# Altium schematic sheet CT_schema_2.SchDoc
size 316 x 200 mm
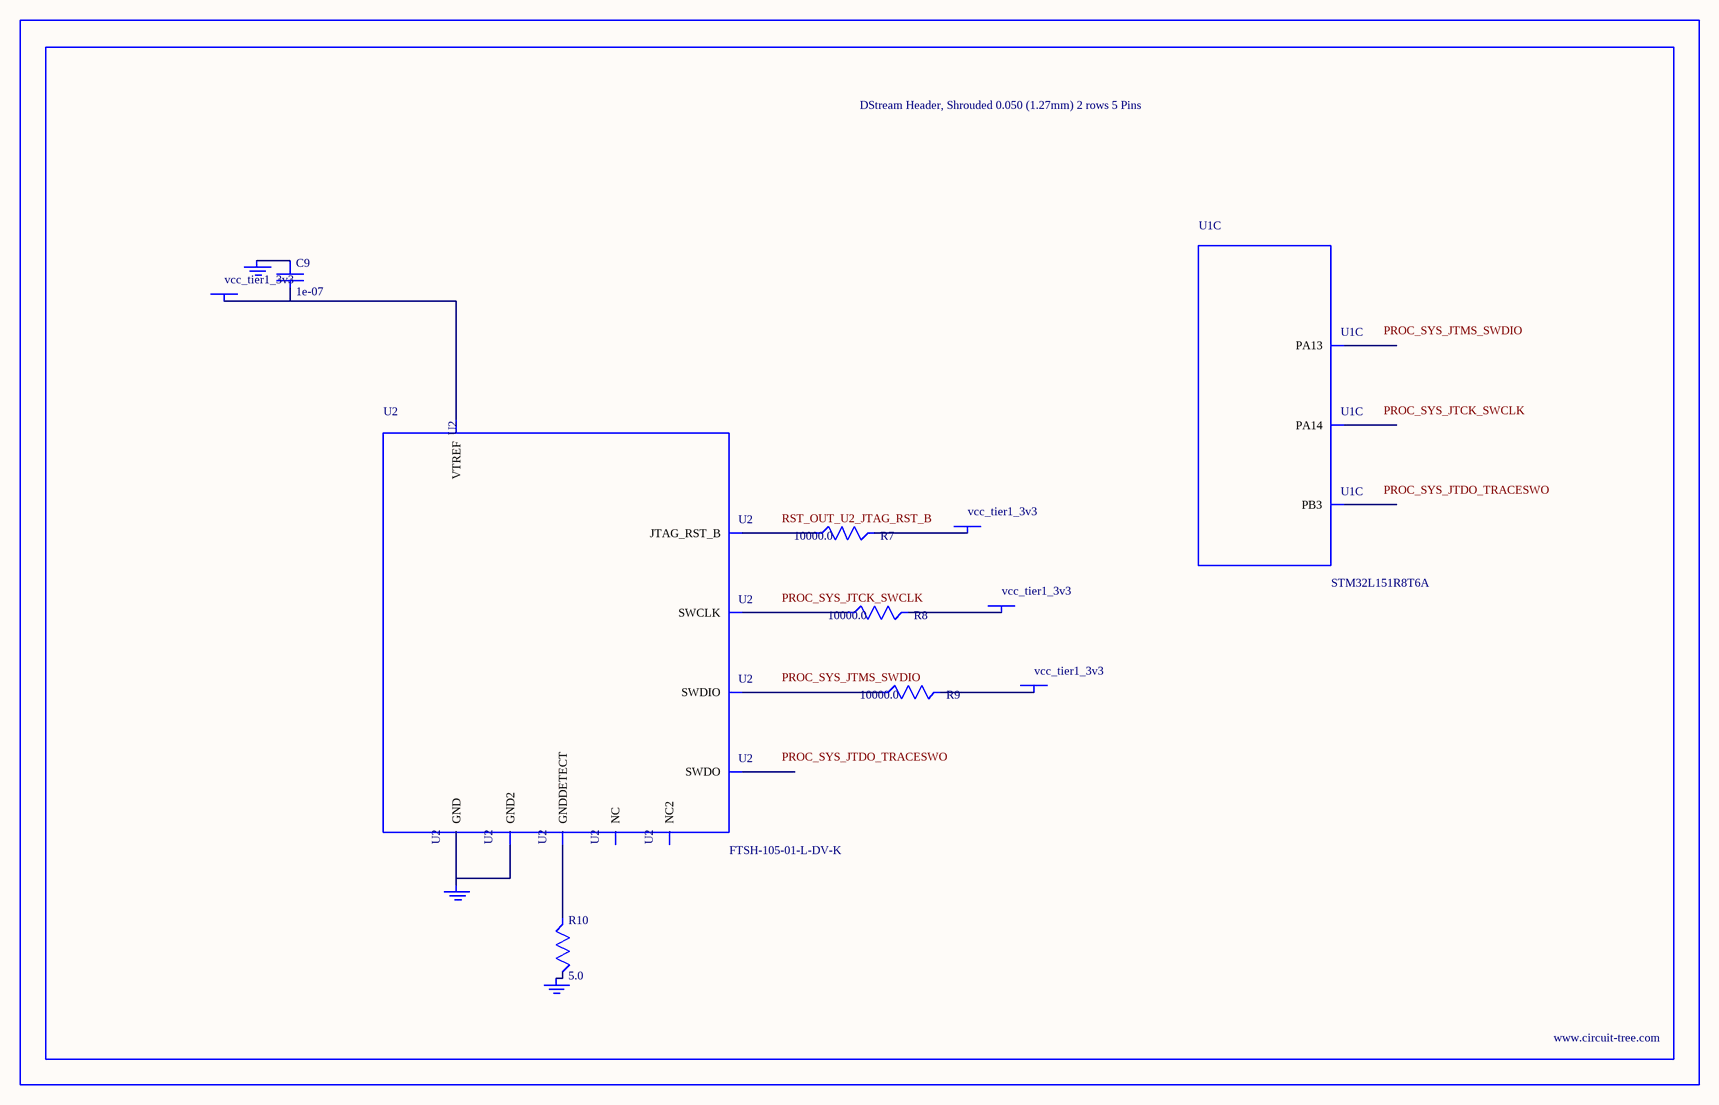
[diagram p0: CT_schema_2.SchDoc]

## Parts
BORDER1  (no value)
C9  1e-07  [C0402]
GND_INSTANCE_1_0  (no value)
GND_INSTANCE_1_1  (no value)
GND_INSTANCE_1_2  (no value)
POWER_INSTANCE_1_0  vcc_tier1_3v3
POWER_INSTANCE_1_1  vcc_tier1_3v3
POWER_INSTANCE_1_2  vcc_tier1_3v3
POWER_INSTANCE_1_3  vcc_tier1_3v3
R7  10000.0  [R0603]
R8  10000.0  [R0603]
R9  10000.0  [R0603]
R10  5.0  [R0603]
U1  STM32L151R8T6A  [LQFP64]  (part C of 7)
U2  FTSH-105-01-L-DV-K  [SAMTEC_FTSH-105-01-L-DV-K]

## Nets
NetC9_1: C9.1 GND_INSTANCE_1_0.0(GND)
NetC9_2: C9.2 POWER_INSTANCE_1_0.0(PWR) U2.1(VTREF)
NetGND_INSTANCE_1_1_0: GND_INSTANCE_1_1.0(GND) R10.2
NetGND_INSTANCE_1_2_0: GND_INSTANCE_1_2.0(GND) U2.3(GND) U2.5(GND2)
NetPOWER_INSTANCE_1_1_0: POWER_INSTANCE_1_1.0(PWR) R9.2
NetPOWER_INSTANCE_1_2_0: POWER_INSTANCE_1_2.0(PWR) R8.2
NetPOWER_INSTANCE_1_3_0: POWER_INSTANCE_1_3.0(PWR) R7.2
NetR7_1: R7.1 U2.10(JTAG_RST_B)
NetR8_1: R8.1 U2.4(SWCLK)
NetR9_1: R9.1 U2.2(SWDIO)
NetR10_1: R10.1 U2.9(GNDDETECT)

Not connected (* = marked no-connect by the designer): U1 46(PA13) 49(PA14) 55(PB3); U2 6(SWDO) 7(NC) 8(NC2)

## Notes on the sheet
- Labels drawn without touching a wire or pin: PROC_SYS_JTCK_SWCLK, PROC_SYS_JTDO_TRACESWO, PROC_SYS_JTMS_SWDIO, RST_OUT_U2_JTAG_RST_B

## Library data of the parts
BORDER1 = BORDER_PAGE1
C9 = C0402C104K3RACTU
GND_INSTANCE_1_0-GND_INSTANCE_1_2 = GND
POWER_INSTANCE_1_0-POWER_INSTANCE_1_3 = PWR
R7-R9 = RC0603JR-0710KL
R10 = ERJ-3GEYJ5R1V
